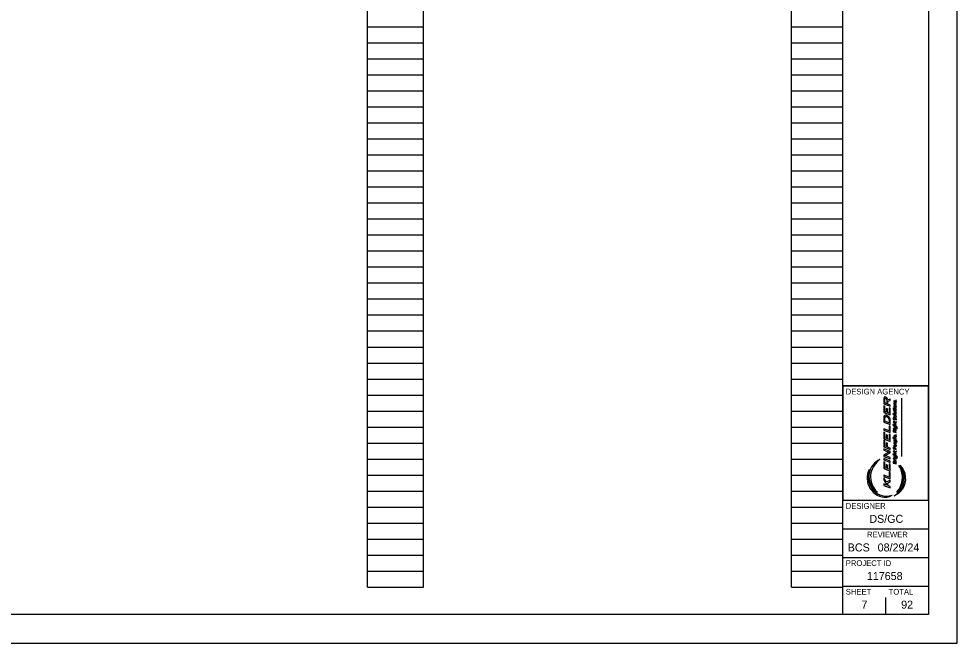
# Model space of a CAD drawing. Extents: x -25 to 34, y -0.5 to 22.
# Drawn here: x 17.58 to 34, y 0 to 10.92 of the extents above; entities that cross this region are included whole.
import ezdxf

# ---------------------------------------------------------------- set-up
doc = ezdxf.new("R2010")
doc.units = 0
for name, color, linetype in [('PV_P_Drive', 7, 'Continuous'), ('SH_Border', 7, 'Continuous'), ('SH_Cut_Line', 7, 'Continuous'), ('SH_Data', 7, 'Continuous'), ('SH_Text', 7, 'Continuous')]:
    doc.layers.add(name, color=color, linetype=linetype)

msp = doc.modelspace()

# ---------------------------------------------------------------- linework, layer by layer
at = {"layer": 'PV_P_Drive'}
for p, q in [((23.68, 0.98), (23.68, 21.14)), ((24.66, 0.98), (24.66, 21.14)), ((31.1, 0.98), (31.1, 21.14)), ((32, 0.98), (32, 21.14)), ((23.68, 10.78), (24.66, 10.78)), ((31.1, 10.78), (32, 10.78)), ((23.68, 10.5), (24.66, 10.5)), ((31.1, 10.5), (32, 10.5)), ((23.68, 10.22), (24.66, 10.22)), ((31.1, 10.22), (32, 10.22)), ((23.68, 9.94), (24.66, 9.94)), ((31.1, 9.94), (32, 9.94)), ((23.68, 9.66), (24.66, 9.66)), ((31.1, 9.66), (32, 9.66)), ((23.68, 9.38), (24.66, 9.38)), ((31.1, 9.38), (32, 9.38)), ((23.68, 9.1), (24.66, 9.1)), ((31.1, 9.1), (32, 9.1)), ((23.68, 8.82), (24.66, 8.82)), ((31.1, 8.82), (32, 8.82)), ((23.68, 8.54), (24.66, 8.54)), ((31.1, 8.54), (32, 8.54)), ((23.68, 8.26), (24.66, 8.26)), ((31.1, 8.26), (32, 8.26)), ((23.68, 7.98), (24.66, 7.98)), ((31.1, 7.98), (32, 7.98)), ((23.68, 7.7), (24.66, 7.7)), ((31.1, 7.7), (32, 7.7)), ((23.68, 7.42), (24.66, 7.42)), ((31.1, 7.42), (32, 7.42)), ((23.68, 7.14), (24.66, 7.14)), ((31.1, 7.14), (32, 7.14)), ((23.68, 6.86), (24.66, 6.86)), ((31.1, 6.86), (32, 6.86)), ((23.68, 6.58), (24.66, 6.58)), ((31.1, 6.58), (32, 6.58)), ((23.68, 6.3), (24.66, 6.3)), ((31.1, 6.3), (32, 6.3)), ((23.68, 6.02), (24.66, 6.02)), ((31.1, 6.02), (32, 6.02)), ((23.68, 5.74), (24.66, 5.74)), ((31.1, 5.74), (32, 5.74)), ((23.68, 5.46), (24.66, 5.46)), ((31.1, 5.46), (32, 5.46)), ((23.68, 5.18), (24.66, 5.18)), ((31.1, 5.18), (32, 5.18)), ((23.68, 4.9), (24.66, 4.9)), ((31.1, 4.9), (32, 4.9)), ((23.68, 4.62), (24.66, 4.62)), ((31.1, 4.62), (32, 4.62)), ((23.68, 4.34), (24.66, 4.34)), ((31.1, 4.34), (32, 4.34)), ((23.68, 4.06), (24.66, 4.06)), ((31.1, 4.06), (32, 4.06)), ((23.68, 3.78), (24.66, 3.78)), ((31.1, 3.78), (32, 3.78)), ((23.68, 3.5), (24.66, 3.5)), ((31.1, 3.5), (32, 3.5)), ((23.68, 3.22), (24.66, 3.22)), ((31.1, 3.22), (32, 3.22)), ((23.68, 2.94), (24.66, 2.94)), ((31.1, 2.94), (32, 2.94)), ((23.68, 2.66), (24.66, 2.66)), ((31.1, 2.66), (32, 2.66)), ((23.68, 2.38), (24.66, 2.38)), ((31.1, 2.38), (32, 2.38)), ((23.68, 2.1), (24.66, 2.1)), ((31.1, 2.1), (32, 2.1)), ((23.68, 1.82), (24.66, 1.82)), ((31.1, 1.82), (32, 1.82)), ((23.68, 1.54), (24.66, 1.54)), ((31.1, 1.54), (32, 1.54)), ((23.68, 1.26), (24.66, 1.26)), ((31.1, 1.26), (32, 1.26)), ((23.68, 0.98), (24.66, 0.98)), ((31.1, 0.98), (32, 0.98))]:
    msp.add_line(p, q, dxfattribs=at)
msp.add_lwpolyline([(32, 2.5), (33.5, 2.5), (33.5, 4.5), (32, 4.5)], close=True, dxfattribs=at)
at = {"layer": 'SH_Border'}
msp.add_lwpolyline([(0, 0), (34, 0), (34, 22), (0, 22)], close=True, dxfattribs=at)
at = {"layer": 'SH_Cut_Line'}
for p, q in [((32, 0.5), (32, 21.5)), ((32, 4.5), (33.5, 4.5)), ((32, 2.5), (33.5, 2.5)), ((32, 2), (33.5, 2)), ((32, 1.5), (33.5, 1.5)), ((32, 1), (33.5, 1))]:
    msp.add_line(p, q, dxfattribs=at)
msp.add_lwpolyline([(1.5, 21.5), (33.5, 21.5), (33.5, 0.5), (1.5, 0.5)], close=True, dxfattribs=at)
at = {"layer": 'SH_Data'}
for p, q in [((32.75, 3.5), (32.75, 3.5)), ((32.375, 0.675), (32.375, 0.675)), ((32.75, 0.5), (32.75, 0.8))]:
    msp.add_line(p, q, dxfattribs=at)
at = {"layer": 'SH_Text'}
for p, q in [((32.735, 4.201), (32.735, 4.271)), ((32.901, 4.239), (32.895, 4.241)), ((32.927, 4.212), (32.933, 4.21)), ((32.888, 3.94), (32.88, 3.942)), ((32.925, 4.077), (32.9, 4.082)), ((32.934, 4.086), (32.928, 4.087)), ((32.936, 3.789), (32.893, 3.798)), ((32.924, 3.905), (32.932, 3.903)), ((32.934, 3.873), (32.928, 3.875)), ((32.902, 3.709), (32.902, 3.699)), ((32.91, 3.626), (32.91, 3.606)), ((32.933, 3.627), (32.926, 3.629)), ((32.942, 3.755), (32.949, 3.753)), ((32.91, 3.463), (32.91, 3.442)), ((32.933, 3.464), (32.926, 3.465)), ((32.905, 3.41), (32.905, 3.403)), ((32.912, 3.402), (32.912, 3.412)), ((32.934, 3.358), (32.928, 3.359)), ((32.936, 3.273), (32.893, 3.282)), ((32.903, 3.161), (32.903, 3.152)), ((32.928, 3.157), (32.928, 3.147)), ((32.942, 3.239), (32.949, 3.237))]:
    msp.add_line(p, q, dxfattribs=at)
for points in [[(32.715, 4.286), (32.715, 4.187), (32.829, 4.143), (32.829, 4.165), (32.787, 4.181), (32.787, 4.232), (32.829, 4.243), (32.829, 4.269), (32.786, 4.259)], [(33.024, 4.283), (33.024, 3.267)], [(32.715, 4.154), (32.715, 4.035), (32.829, 3.992), (32.829, 4.111), (32.809, 4.119), (32.809, 4.023), (32.78, 4.034), (32.78, 4.099), (32.759, 4.107), (32.759, 4.042), (32.735, 4.051), (32.735, 4.147), (32.715, 4.154)], [(32.766, 4.257), (32.766, 4.189), (32.735, 4.201)], [(32.877, 4.114), (32.877, 4.106), (32.885, 4.104), (32.885, 4.113), (32.877, 4.114)], [(32.899, 4.179), (32.893, 4.18), (32.893, 4.173), (32.934, 4.164), (32.934, 4.172), (32.911, 4.177)], [(32.893, 4.111), (32.893, 4.103), (32.934, 4.094), (32.934, 4.102), (32.893, 4.111)], [(32.906, 4.199), (32.934, 4.193), (32.934, 4.201), (32.909, 4.207)], [(32.926, 4.255), (32.926, 4.247), (32.934, 4.245), (32.934, 4.253), (32.926, 4.255)], [(32.715, 3.948), (32.715, 3.867), (32.829, 3.824), (32.829, 3.897)], [(32.808, 3.906), (32.808, 3.855), (32.736, 3.882), (32.736, 3.942)], [(32.875, 4.013), (32.875, 4.005), (32.934, 3.993), (32.934, 4.001), (32.875, 4.013)], [(32.9, 4.082), (32.9, 4.093), (32.893, 4.094), (32.893, 4.083), (32.881, 4.086), (32.884, 4.078), (32.893, 4.076), (32.893, 4.067), (32.9, 4.065), (32.9, 4.074), (32.924, 4.069)], [(32.928, 4.044), (32.934, 4.043), (32.934, 4.05), (32.893, 4.059), (32.893, 4.051), (32.917, 4.046)], [(32.921, 4.024), (32.893, 4.03), (32.893, 4.022), (32.918, 4.017)], [(32.715, 3.752), (32.715, 3.728), (32.829, 3.685), (32.829, 3.793), (32.809, 3.801), (32.809, 3.717), (32.715, 3.752)], [(32.898, 3.818), (32.874, 3.823), (32.874, 3.815), (32.934, 3.802), (32.934, 3.81), (32.913, 3.815)], [(32.893, 3.882), (32.893, 3.871), (32.881, 3.874), (32.884, 3.865), (32.893, 3.863), (32.893, 3.854), (32.9, 3.853), (32.9, 3.862), (32.924, 3.857)], [(32.925, 3.864), (32.9, 3.87), (32.9, 3.881), (32.893, 3.882)], [(32.893, 3.798), (32.893, 3.79), (32.9, 3.789)], [(32.908, 3.836), (32.934, 3.831), (32.934, 3.839), (32.908, 3.844)], [(32.759, 3.644), (32.759, 3.579), (32.735, 3.588), (32.735, 3.683), (32.715, 3.691), (32.715, 3.572), (32.829, 3.529), (32.829, 3.648), (32.809, 3.656), (32.809, 3.56), (32.78, 3.571), (32.78, 3.636), (32.759, 3.644)], [(32.877, 3.753), (32.877, 3.745), (32.885, 3.743), (32.885, 3.751), (32.877, 3.753)], [(32.879, 3.716), (32.879, 3.696), (32.934, 3.684), (32.934, 3.692), (32.909, 3.698), (32.909, 3.705)], [(32.902, 3.699), (32.885, 3.703), (32.885, 3.711)], [(32.893, 3.749), (32.893, 3.741), (32.934, 3.732), (32.934, 3.741), (32.893, 3.749)], [(32.914, 3.711), (32.934, 3.716), (32.934, 3.724), (32.911, 3.717)], [(32.92, 3.605), (32.916, 3.605), (32.916, 3.634), (32.913, 3.634)], [(32.926, 3.65), (32.926, 3.642), (32.934, 3.64), (32.934, 3.648), (32.926, 3.65)], [(32.759, 3.504), (32.759, 3.439), (32.736, 3.448), (32.736, 3.544), (32.715, 3.552), (32.715, 3.433), (32.829, 3.389), (32.829, 3.413), (32.78, 3.431), (32.78, 3.497), (32.759, 3.504)], [(32.875, 3.595), (32.875, 3.587), (32.934, 3.574), (32.934, 3.582), (32.875, 3.595)], [(32.899, 3.538), (32.893, 3.539), (32.893, 3.532), (32.951, 3.52), (32.951, 3.528), (32.929, 3.533)], [(32.92, 3.441), (32.916, 3.441), (32.916, 3.47), (32.913, 3.471)], [(32.715, 3.295), (32.715, 3.267), (32.829, 3.223), (32.829, 3.247), (32.741, 3.28), (32.829, 3.327), (32.829, 3.355), (32.715, 3.399), (32.715, 3.375), (32.802, 3.341), (32.715, 3.295)], [(32.898, 3.302), (32.874, 3.307), (32.874, 3.299), (32.934, 3.286), (32.934, 3.294), (32.913, 3.299)], [(32.879, 3.418), (32.879, 3.4), (32.934, 3.389), (32.934, 3.397), (32.912, 3.402)], [(32.893, 3.366), (32.893, 3.355), (32.881, 3.358), (32.884, 3.349), (32.893, 3.348), (32.893, 3.338), (32.9, 3.337), (32.9, 3.346), (32.924, 3.341)], [(32.905, 3.403), (32.885, 3.407), (32.885, 3.414)], [(32.925, 3.348), (32.9, 3.354), (32.9, 3.365), (32.893, 3.366)], [(32.908, 3.321), (32.934, 3.315), (32.934, 3.323), (32.908, 3.328)], [(32.715, 3.229), (32.715, 3.206), (32.829, 3.162), (32.829, 3.185), (32.715, 3.229)], [(32.715, 3.172), (32.715, 3.053), (32.829, 3.009), (32.829, 3.128), (32.809, 3.136), (32.809, 3.041), (32.78, 3.052), (32.78, 3.116), (32.759, 3.124), (32.759, 3.059), (32.735, 3.068), (32.735, 3.164), (32.715, 3.172)], [(32.877, 3.237), (32.877, 3.229), (32.885, 3.227), (32.885, 3.235), (32.877, 3.237)], [(32.879, 3.168), (32.879, 3.149), (32.934, 3.137), (32.934, 3.16)], [(32.903, 3.152), (32.885, 3.156), (32.885, 3.164)], [(32.893, 3.282), (32.893, 3.274), (32.9, 3.273)], [(32.893, 3.233), (32.893, 3.225), (32.934, 3.216), (32.934, 3.225), (32.893, 3.233)], [(32.9, 3.215), (32.893, 3.216), (32.893, 3.209)], [(32.899, 3.2), (32.893, 3.201), (32.893, 3.193), (32.934, 3.185), (32.934, 3.192), (32.911, 3.197)], [(32.928, 3.147), (32.909, 3.151), (32.909, 3.16)], [(32.715, 2.941), (32.715, 2.917), (32.829, 2.874), (32.829, 2.982), (32.809, 2.99), (32.809, 2.906), (32.715, 2.941)], [(32.715, 2.895), (32.715, 2.859), (32.769, 2.765), (32.715, 2.785), (32.715, 2.761), (32.829, 2.718), (32.829, 2.742), (32.795, 2.755), (32.772, 2.794), (32.829, 2.824), (32.829, 2.853), (32.76, 2.816), (32.715, 2.895)]]:
    msp.add_lwpolyline(points, dxfattribs=at)
for centre, radius, start, end in [((32.738, 4.285), 0.0235, 105.8602, 175.9527), ((32.734, 4.272), 0.0359, 63.9111, 93.4134), ((32.746, 4.272), 0.0116, 120.9282, 182.8587), ((32.744, 4.27), 0.0128, 71.295, 106.2465), ((32.739, 4.256), 0.0278, 3.188, 69.9483), ((32.728, 4.249), 0.059, 10.1322, 68.6534), ((32.907, 4.193), 0.0143, 136.2913, 182.0825), ((32.908, 4.192), 0.0157, 176.9051, 236.2062), ((32.916, 4.231), 0.0237, 155.8068, 177.518), ((32.909, 4.23), 0.0164, 172.9331, 212.9177), ((32.913, 4.141), 0.0207, 134.8616, 186.3333), ((32.914, 4.14), 0.0218, 183.0085, 235.1138), ((32.904, 4.225), 0.0102, 205.2791, 253.4117), ((32.906, 4.191), 0.0157, 78.3727, 128.7252), ((32.908, 4.231), 0.0105, 131.8722, 213.0859), ((32.909, 4.192), 0.0107, 164.3628, 217.5642), ((32.908, 4.141), 0.00982, 114.8029, 183.3912), ((32.91, 4.14), 0.0115, 178.7964, 222.8298), ((32.905, 4.191), 0.00751, 82.4034, 156.5016), ((32.911, 4.135), 0.0236, 80.4774, 121.3769), ((32.904, 4.228), 0.00472, 212.4264, 286.081), ((32.916, 4.196), 0.0192, 214.0093, 253.9548), ((32.917, 4.147), 0.0212, 222.6118, 267.8201), ((32.904, 4.225), 0.0096, 252.4577, 305.4949), ((32.915, 4.14), 0.0225, 234.7204, 275.0527), ((32.911, 4.134), 0.0176, 73.9781, 113.6531), ((32.9, 4.234), 0.0117, 294.6007, 337.5251), ((32.899, 4.232), 0.018, 306.3564, 329.8219), ((32.924, 4.224), 0.0139, 114.5985, 155.8852), ((32.937, 4.21), 0.0248, 133.1465, 150.3389), ((32.913, 4.137), 0.0217, 48.9189, 86.1506), ((32.911, 4.131), 0.0201, 30.777, 75.0314), ((32.918, 4.138), 0.0124, 261.6619, 324.7522), ((32.919, 4.134), 0.0164, 263.7465, 315.576), ((32.923, 4.224), 0.013, 67.7239, 111.621), ((32.923, 4.225), 0.00487, 54.9774, 133.6656), ((32.921, 4.222), 0.0081, 0.828, 56.4407), ((32.914, 4.221), 0.0154, 324.4952, 5.8801), ((32.919, 4.223), 0.0157, 25.7964, 57.936), ((32.917, 4.139), 0.0181, 359.1065, 54.0048), ((32.917, 4.136), 0.0122, 333.802, 26.7946), ((32.916, 4.135), 0.0192, 318.3025, 9.3316), ((32.917, 4.222), 0.0183, 351.4651, 24.96), ((32.894, 4.224), 0.0413, 341.1844, 354.3531), ((32.763, 3.948), 0.0481, 135.8191, 179.4263), ((32.749, 3.952), 0.0358, 73.1779, 125.9306), ((32.756, 3.942), 0.0203, 112.5545, 180.292), ((32.755, 3.943), 0.0192, 70.7496, 111.8258), ((32.736, 3.898), 0.0911, 25.2799, 75.3517), ((32.747, 3.901), 0.0624, 24.8644, 76.4065), ((32.902, 3.931), 0.0246, 153.0923, 182.7278), ((32.913, 3.969), 0.0207, 134.8616, 186.3333), ((32.914, 3.967), 0.0218, 183.0085, 235.1138), ((32.908, 3.969), 0.00982, 114.8029, 183.3912), ((32.91, 3.968), 0.0115, 178.7964, 222.8298), ((32.911, 3.963), 0.0236, 80.4774, 121.3769), ((32.917, 3.974), 0.0212, 222.6118, 267.8201), ((32.915, 3.968), 0.0225, 234.7204, 275.0527), ((32.911, 3.961), 0.0176, 73.9781, 113.6531), ((32.913, 3.965), 0.0217, 48.9189, 86.1506), ((32.911, 3.959), 0.0201, 30.777, 75.0314), ((32.918, 3.966), 0.0124, 261.6619, 324.7522), ((32.911, 4.028), 0.0192, 34.0093, 73.9548), ((32.919, 3.962), 0.0164, 263.7465, 315.576), ((32.922, 4.032), 0.0157, 258.3727, 308.7252), ((32.922, 4.032), 0.00751, 262.4034, 336.5016), ((32.926, 4.078), 0.00899, 258.837, 329.2244), ((32.926, 4.081), 0.00406, 265.2766, 359.8271), ((32.919, 4.032), 0.0107, 344.3628, 37.5642), ((32.918, 4.081), 0.012, 359.8271, 33.4272), ((32.92, 4.031), 0.0157, 356.9051, 56.2062), ((32.917, 3.966), 0.0181, 359.1065, 54.0048), ((32.917, 3.964), 0.0122, 333.802, 26.7946), ((32.916, 3.963), 0.0192, 318.3025, 9.3316), ((32.921, 4.03), 0.0143, 316.2913, 2.0825), ((32.914, 4.081), 0.0207, 339.7319, 13.8876), ((32.763, 3.907), 0.0458, 358.9317, 26.1463), ((32.744, 3.896), 0.0851, 0.5101, 28.8607), ((32.914, 3.931), 0.0359, 182.7278, 201.3007), ((32.894, 3.926), 0.0157, 207.7495, 253.8409), ((32.899, 3.93), 0.0144, 140.4782, 179.939), ((32.897, 3.929), 0.0124, 175.3728, 230.5265), ((32.893, 3.928), 0.00909, 239.5135, 284.896), ((32.893, 3.926), 0.0158, 256.3758, 294.8902), ((32.909, 3.83), 0.017, 145.2436, 189.7855), ((32.912, 3.776), 0.0195, 166.4234, 246.8498), ((32.905, 3.829), 0.0129, 185.2859, 235.9293), ((32.904, 3.778), 0.0113, 111.6426, 168.888), ((32.906, 3.83), 0.0141, 80.6828, 137.5266), ((32.888, 3.932), 0.0149, 299.565, 339.2556), ((32.907, 3.828), 0.00818, 136.5529, 210.7681), ((32.909, 3.777), 0.0102, 156.145, 220.58), ((32.909, 3.776), 0.0105, 93.2154, 153.4686), ((32.887, 3.931), 0.0238, 303.1236, 337.1341), ((32.917, 3.835), 0.0202, 210.678, 259.5619), ((32.906, 3.829), 0.00748, 78.1668, 139.4713), ((32.921, 3.918), 0.0202, 112.5492, 156.2929), ((32.91, 3.764), 0.0226, 65.4895, 96.081), ((32.919, 3.918), 0.011, 90.8577, 158.2517), ((32.918, 3.92), 0.018, 58.4507, 105.0331), ((32.918, 3.919), 0.0099, 7.9705, 84.8943), ((32.916, 3.773), 0.0125, 4.6127, 71.2311), ((32.909, 3.917), 0.0192, 321.116, 10.1848), ((32.926, 3.866), 0.00899, 258.837, 329.2244), ((32.926, 3.868), 0.00406, 265.2766, 359.8271), ((32.915, 3.919), 0.0199, 358.5943, 53.7031), ((32.918, 3.868), 0.012, 359.8271, 33.4272), ((32.919, 3.772), 0.0154, 347.3096, 45.7047), ((32.929, 3.764), 0.0181, 52.9431, 88.3704), ((32.903, 3.918), 0.0327, 332.8538, 1.7076), ((32.914, 3.869), 0.0207, 339.7319, 13.8876), ((32.933, 3.771), 0.0178, 23.5672, 81.0788), ((32.93, 3.767), 0.0158, 15.8406, 51.2557), ((32.921, 3.767), 0.0312, 334.3125, 21.7018), ((32.893, 3.714), 0.0143, 114.3537, 174.3612), ((32.895, 3.711), 0.00918, 126.0182, 180.1757), ((32.891, 3.712), 0.0163, 54.324, 105.2141), ((32.893, 3.708), 0.0111, 71.543, 108.457), ((32.905, 3.622), 0.0124, 112.1338, 170.4587), ((32.915, 3.619), 0.0226, 169.5031, 205.801), ((32.891, 3.709), 0.0113, 2.8048, 63.3705), ((32.907, 3.618), 0.00858, 117.3851, 158.6637), ((32.91, 3.619), 0.0119, 168.1247, 206.2564), ((32.912, 3.619), 0.0135, 203.2444, 260.0416), ((32.917, 3.786), 0.0229, 224.9845, 280.2941), ((32.89, 3.71), 0.0187, 16.6516, 54.9416), ((32.909, 3.609), 0.0257, 81.9878, 109.8531), ((32.907, 3.615), 0.012, 75.5066, 109.4211), ((32.916, 3.782), 0.0268, 243.1201, 290.541), ((32.913, 3.712), 0.00573, 112.0732, 152.0788), ((32.915, 3.705), 0.00539, 102.6271, 185.8955), ((32.92, 3.772), 0.00874, 280.0175, 10.7991), ((32.919, 3.771), 0.0158, 297.2493, 349.812), ((32.892, 3.614), 0.0374, 10.3368, 23.7103), ((32.91, 3.618), 0.0187, 328.9592, 8.5627), ((32.916, 3.614), 0.0192, 319.8498, 2.5151), ((32.888, 3.615), 0.047, 359.6882, 15.2269), ((32.927, 3.767), 0.0194, 322.3021, 11.6769), ((32.908, 3.552), 0.016, 128.4644, 186.7325), ((32.91, 3.552), 0.0179, 186.9887, 232.7091), ((32.913, 3.5), 0.0207, 134.8616, 186.3333), ((32.914, 3.499), 0.0218, 183.0085, 235.1138), ((32.905, 3.458), 0.0124, 112.1338, 170.4587), ((32.915, 3.456), 0.0226, 169.5031, 205.801), ((32.916, 3.62), 0.0231, 206.9109, 260.8013), ((32.907, 3.55), 0.00899, 131.5529, 215.9721), ((32.908, 3.501), 0.00982, 114.8029, 183.3912), ((32.91, 3.5), 0.0115, 178.7964, 222.8298), ((32.91, 3.54), 0.0268, 74.1204, 115.3732), ((32.911, 3.495), 0.0236, 80.4774, 121.3769), ((32.907, 3.455), 0.00858, 117.3851, 158.6637), ((32.91, 3.455), 0.0119, 168.1247, 206.2564), ((32.916, 3.554), 0.0182, 210.6491, 255.0946), ((32.912, 3.455), 0.0135, 203.2444, 260.0416), ((32.91, 3.547), 0.0133, 76.6402, 131.7242), ((32.917, 3.506), 0.0212, 222.6118, 267.8201), ((32.909, 3.445), 0.0257, 81.9878, 109.8531), ((32.915, 3.5), 0.0225, 234.7204, 275.0527), ((32.907, 3.451), 0.012, 75.5066, 109.4211), ((32.911, 3.493), 0.0176, 73.9781, 113.6531), ((32.917, 3.552), 0.0167, 247.995, 291.3144), ((32.917, 3.618), 0.0209, 255.6438, 310.1539), ((32.911, 3.539), 0.0207, 43.01, 84.1033), ((32.913, 3.497), 0.0217, 48.9189, 86.1506), ((32.911, 3.491), 0.0201, 30.777, 75.0314), ((32.918, 3.497), 0.0124, 261.6619, 324.7522), ((32.914, 3.544), 0.0228, 23.9558, 80.548), ((32.919, 3.494), 0.0164, 263.7465, 315.576), ((32.918, 3.617), 0.0122, 278.9982, 314.1507), ((32.918, 3.546), 0.0114, 295.6576, 343.4617), ((32.919, 3.545), 0.0101, 346.7314, 48.3063), ((32.892, 3.45), 0.0374, 10.3368, 23.7103), ((32.91, 3.454), 0.0187, 328.9592, 8.5627), ((32.917, 3.498), 0.0181, 359.1065, 54.0048), ((32.917, 3.496), 0.0122, 333.802, 26.7946), ((32.917, 3.547), 0.0184, 309.5558, 17.4679), ((32.916, 3.495), 0.0192, 318.3025, 9.3316), ((32.916, 3.45), 0.0192, 319.8498, 2.5151), ((32.888, 3.451), 0.047, 359.6882, 15.2269), ((32.894, 3.417), 0.0158, 126.8786, 177.6793), ((32.893, 3.414), 0.0183, 67.3357, 118.1453), ((32.895, 3.415), 0.00934, 123.5007, 184.662), ((32.894, 3.412), 0.0119, 57.2999, 110.5503), ((32.909, 3.314), 0.017, 145.2436, 189.7855), ((32.905, 3.313), 0.0129, 185.2859, 235.9293), ((32.916, 3.456), 0.0231, 206.9109, 260.8013), ((32.906, 3.314), 0.0141, 80.6828, 137.5266), ((32.907, 3.312), 0.00818, 136.5529, 210.7681), ((32.89, 3.411), 0.0145, 357.8598, 47.6882), ((32.917, 3.319), 0.0202, 210.678, 259.5619), ((32.893, 3.413), 0.0192, 355.6807, 65.6249), ((32.906, 3.313), 0.00748, 78.1668, 139.4713), ((32.917, 3.454), 0.0209, 255.6438, 310.1539), ((32.918, 3.453), 0.0122, 278.9982, 314.1507), ((32.926, 3.35), 0.00899, 258.837, 329.2244), ((32.926, 3.352), 0.00406, 265.2766, 359.8271), ((32.918, 3.352), 0.012, 359.8271, 33.4272), ((32.914, 3.353), 0.0207, 339.7319, 13.8876), ((32.792, 2.906), 0.34, 115.1143, 168.3777), ((32.871, 2.888), 0.394, 124.4536, 166.9641), ((32.893, 3.167), 0.0148, 118.8217, 177.6001), ((32.893, 3.165), 0.00845, 104.5669, 183.2204), ((32.891, 3.164), 0.0165, 47.423, 108.0377), ((32.893, 3.165), 0.0084, 40.2808, 100.5581), ((32.912, 3.26), 0.0195, 166.4234, 246.8498), ((32.904, 3.262), 0.0113, 111.6426, 168.888), ((32.907, 3.211), 0.0136, 188.2387, 237.9511), ((32.909, 3.261), 0.0102, 156.145, 220.58), ((32.909, 3.26), 0.0105, 93.2154, 153.4686), ((32.909, 3.211), 0.00995, 158.8231, 202.4085), ((32.887, 3.16), 0.0155, 3.7446, 38.6277), ((32.917, 3.216), 0.0194, 205.713, 250.7037), ((32.917, 3.27), 0.0229, 224.9845, 280.2941), ((32.886, 3.166), 0.0195, 8.6642, 31.5112), ((32.916, 3.266), 0.0268, 243.1201, 290.541), ((32.917, 3.165), 0.0129, 99.5096, 160.7154), ((32.91, 3.248), 0.0226, 65.4895, 96.081), ((32.917, 3.161), 0.00818, 113.2405, 191.7775), ((32.917, 3.162), 0.00788, 58.3862, 113.2405), ((32.918, 3.165), 0.0131, 56.795, 103.6323), ((32.916, 3.257), 0.0125, 4.6127, 71.2311), ((32.92, 3.256), 0.00874, 280.0175, 10.7991), ((32.914, 3.157), 0.0135, 1.8674, 60.8259), ((32.914, 3.159), 0.0207, 4.8421, 55.7541), ((32.919, 3.255), 0.0158, 297.2493, 349.812), ((32.919, 3.256), 0.0154, 347.3096, 45.7047), ((32.929, 3.249), 0.0181, 52.9431, 88.3704), ((32.933, 3.255), 0.0178, 23.5672, 81.0788), ((32.93, 3.251), 0.0158, 15.8406, 51.2557), ((32.927, 3.251), 0.0194, 322.3021, 11.6769), ((32.921, 3.251), 0.0312, 334.3125, 21.7018), ((32.756, 2.885), 0.333, 153.0899, 211.3353), ((32.801, 2.913), 0.363, 160.2384, 179.8908), ((32.792, 2.92), 0.337, 170.6744, 236.0558), ((32.855, 2.915), 0.373, 170.3407, 217.7725), ((32.599, 2.884), 0.443, 1.2686, 30.3182), ((32.706, 2.894), 0.347, 356.3155, 37.8631), ((32.771, 2.881), 0.328, 325.1289, 45.2058), ((32.7, 2.891), 0.376, 357.0055, 36.4292), ((32.771, 2.881), 0.328, 325.1289, 45.2058), ((32.7, 2.891), 0.376, 357.0055, 36.4292), ((32.832, 2.928), 0.394, 182.1375, 213.7556), ((32.705, 2.894), 0.37, 301.6203, 356.4398), ((32.705, 2.894), 0.37, 301.6203, 356.4398), ((32.626, 2.909), 0.415, 319.4476, 357.9721), ((32.706, 2.894), 0.348, 312.6314, 356.3155), ((32.755, 2.881), 0.33, 210.9374, 272.3516), ((32.761, 2.887), 0.313, 214.7279, 288.5434), ((32.804, 2.875), 0.309, 217.7725, 229.547), ((32.768, 2.883), 0.331, 293.3176, 325.0704), ((32.768, 2.883), 0.331, 293.3176, 325.0704), ((32.719, 2.797), 0.25, 281.4129, 304.5262)]:
    msp.add_arc(centre, radius, start, end, dxfattribs=at)

# ---------------------------------------------------------------- texts
at = {"layer": 'SH_Data'}
for s, height, p in [('DESIGN AGENCY', 0.1, (32.05, 4.35)), ('DESIGNER', 0.1, (32.05, 2.35)), ('DS/GC', 0.14, (32.463, 2.105)), ('REVIEWER', 0.1, (32.422, 1.85)), ('BCS', 0.14, (32.084, 1.605)), ('08/29/24', 0.14, (32.608, 1.605)), ('PROJECT ID', 0.1, (32.05, 1.35)), ('117658', 0.14, (32.419, 1.105)), ('SHEET', 0.1, (32.05, 0.85)), ('TOTAL', 0.1, (32.8, 0.85)), ('7', 0.14, (32.324, 0.605)), ('92', 0.14, (33.019, 0.605))]:
    msp.add_text(s, height=height, dxfattribs=at).set_placement(p)

doc.saveas('drawing.dxf')
